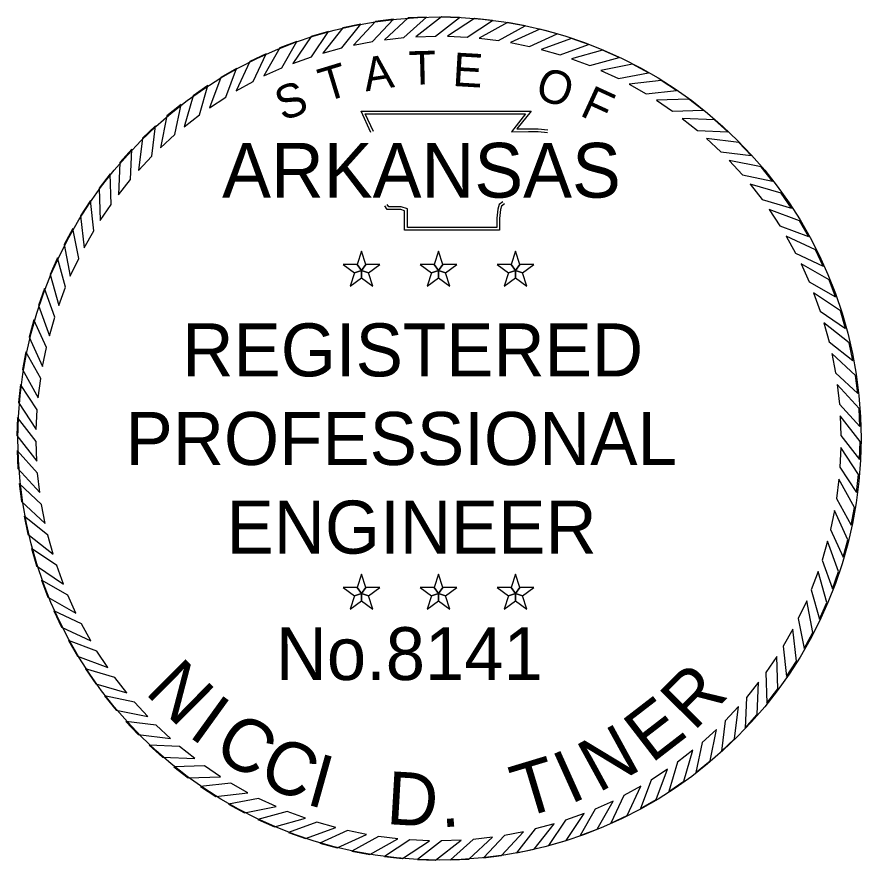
# Model space of a CAD drawing. Extents: x 0 to 19, y -0.6 to 11.2.
# Drawn here: x 17.822 to 19.023, y 9.084 to 10.284 of the extents above; entities that cross this region are included whole.
import ezdxf

# ---------------------------------------------------------------- set-up
doc = ezdxf.new("R2010")
doc.units = 0
doc.layers.add('G-ANNO-STMP', color=7, linetype='Continuous')
doc.layers.add('G-No Plot-Stamp-1', color=7, linetype='Continuous')

msp = doc.modelspace()

# ---------------------------------------------------------------- linework, layer by layer
at = {"layer": 'G-ANNO-STMP'}
for points in [[(18.3112, 10.2732), (18.2859, 10.2679), (18.2573, 10.2319), (18.2842, 10.2393)], [(18.3578, 10.2801), (18.3322, 10.2768), (18.3008, 10.2431), (18.3282, 10.2484)], [(18.4048, 10.2833), (18.379, 10.282), (18.3451, 10.2509), (18.3728, 10.254)], [(18.4519, 10.2828), (18.4261, 10.2835), (18.3899, 10.2552), (18.4177, 10.2561)], [(18.4988, 10.2786), (18.4732, 10.2813), (18.4348, 10.256), (18.4627, 10.2546)], [(18.5453, 10.2707), (18.5199, 10.2755), (18.4797, 10.2532), (18.5073, 10.2497)], [(18.2652, 10.2627), (18.2405, 10.2554), (18.2148, 10.2173), (18.241, 10.2268)], [(18.591, 10.2592), (18.5661, 10.266), (18.5242, 10.2469), (18.5515, 10.2412)], [(18.2203, 10.2486), (18.1962, 10.2394), (18.1735, 10.1994), (18.1989, 10.2109)], [(18.6356, 10.2442), (18.6113, 10.2529), (18.5681, 10.2371), (18.5949, 10.2294)], [(18.6789, 10.2257), (18.6554, 10.2362), (18.6111, 10.224), (18.6372, 10.2141)], [(18.1766, 10.2311), (18.1533, 10.22), (18.1338, 10.1783), (18.1582, 10.1918)], [(18.7207, 10.2039), (18.698, 10.2162), (18.6529, 10.2074), (18.6781, 10.1956)], [(18.1344, 10.2101), (18.112, 10.1973), (18.0959, 10.1542), (18.1192, 10.1695)], [(18.7606, 10.1788), (18.739, 10.1929), (18.6933, 10.1877), (18.7175, 10.1739)], [(18.0939, 10.1859), (18.0726, 10.1714), (18.06, 10.1272), (18.082, 10.1443)], [(18.7984, 10.1507), (18.778, 10.1665), (18.732, 10.1649), (18.7551, 10.1492)], [(18.0555, 10.1587), (18.0354, 10.1425), (18.0263, 10.0974), (18.0469, 10.1162)], [(18.0194, 10.1284), (18.0006, 10.1107), (17.995, 10.0651), (18.0141, 10.0854)], [(18.8339, 10.1197), (18.8148, 10.137), (18.7688, 10.1391), (18.7906, 10.1216)], [(18.8669, 10.0861), (18.8491, 10.1048), (18.8035, 10.1104), (18.8238, 10.0914)], [(17.9857, 10.0955), (17.9684, 10.0764), (17.9664, 10.0304), (17.9838, 10.0522)], [(18.8971, 10.0499), (18.8809, 10.07), (18.8358, 10.0792), (18.8546, 10.0586)], [(17.9547, 10.06), (17.939, 10.0396), (17.9406, 9.9936), (17.9562, 10.0167)], [(18.9244, 10.0115), (18.9098, 10.0328), (18.8656, 10.0455), (18.8827, 10.0235)], [(17.9266, 10.0222), (17.9125, 10.0006), (17.9177, 9.9549), (17.9315, 9.9791)], [(18.9485, 9.9711), (18.9357, 9.9935), (18.8926, 10.0096), (18.9079, 9.9863)], [(17.9016, 9.9823), (17.8892, 9.9596), (17.898, 9.9145), (17.9099, 9.9397)], [(18.9695, 9.9289), (18.9584, 9.9522), (18.9167, 9.9716), (18.9302, 9.9472)], [(18.3122, 9.9224), (18.3184, 9.9309), (18.3122, 9.9499), (18.3061, 9.9309)], [(18.4219, 9.9224), (18.4281, 9.9309), (18.4219, 9.9499), (18.4158, 9.9309)], [(18.5317, 9.9224), (18.5378, 9.9309), (18.5317, 9.9499), (18.5255, 9.9309)], [(17.8798, 9.9405), (17.8692, 9.917), (17.8815, 9.8727), (17.8913, 9.8987)], [(18.3122, 9.9224), (18.3061, 9.9309), (18.2861, 9.9309), (18.3023, 9.9192)], [(18.3122, 9.9224), (18.3222, 9.9192), (18.3383, 9.9309), (18.3184, 9.9309)], [(18.4219, 9.9224), (18.4158, 9.9309), (18.3958, 9.9309), (18.412, 9.9192)], [(18.4219, 9.9224), (18.4319, 9.9192), (18.448, 9.9309), (18.4281, 9.9309)], [(18.5317, 9.9224), (18.5255, 9.9309), (18.5056, 9.9309), (18.5217, 9.9192)], [(18.5317, 9.9224), (18.5416, 9.9192), (18.5577, 9.9309), (18.5378, 9.9309)], [(18.987, 9.8852), (18.9779, 9.9093), (18.9378, 9.9319), (18.9493, 9.9065)], [(18.3122, 9.9224), (18.3023, 9.9192), (18.2961, 9.9003), (18.3122, 9.912)], [(18.3122, 9.9224), (18.3122, 9.912), (18.3283, 9.9003), (18.3222, 9.9192)], [(18.4219, 9.9224), (18.412, 9.9192), (18.4058, 9.9003), (18.4219, 9.912)], [(18.4219, 9.9224), (18.4219, 9.912), (18.4381, 9.9003), (18.4319, 9.9192)], [(18.5317, 9.9224), (18.5217, 9.9192), (18.5155, 9.9003), (18.5317, 9.912)], [(18.5317, 9.9224), (18.5317, 9.912), (18.5478, 9.9003), (18.5416, 9.9192)], [(17.8613, 9.8972), (17.8526, 9.8729), (17.8683, 9.8297), (17.8761, 9.8564)], [(19.0011, 9.8402), (18.9939, 9.865), (18.9557, 9.8907), (18.9652, 9.8645)], [(17.8462, 9.8525), (17.8395, 9.8276), (17.8586, 9.7858), (17.8642, 9.8131)], [(19.0116, 9.7943), (19.0063, 9.8195), (18.9703, 9.8482), (18.9777, 9.8213)], [(17.8347, 9.8069), (17.83, 9.7815), (17.8523, 9.7413), (17.8558, 9.7689)], [(19.0185, 9.7477), (19.0152, 9.7733), (18.9816, 9.8046), (18.9868, 9.7772)], [(17.8269, 9.7604), (17.8241, 9.7347), (17.8495, 9.6964), (17.8508, 9.7242)], [(19.0217, 9.7007), (19.0204, 9.7264), (18.9893, 9.7603), (18.9924, 9.7326)], [(17.8227, 9.7135), (17.8219, 9.6877), (17.8503, 9.6514), (17.8494, 9.6793)], [(19.0212, 9.6536), (19.0219, 9.6793), (18.9936, 9.7156), (18.9945, 9.6877)], [(17.8222, 9.6664), (17.8235, 9.6406), (17.8545, 9.6067), (17.8515, 9.6344)], [(19.017, 9.6066), (19.0198, 9.6323), (18.9944, 9.6706), (18.9931, 9.6428)], [(19.0091, 9.5602), (19.0139, 9.5855), (18.9916, 9.6258), (18.9881, 9.5981)], [(17.8254, 9.6194), (17.8287, 9.5938), (17.8623, 9.5624), (17.8571, 9.5898)], [(18.9976, 9.5145), (19.0044, 9.5394), (18.9853, 9.5812), (18.9797, 9.5539)], [(17.8322, 9.5728), (17.8375, 9.5475), (17.8735, 9.5189), (17.8662, 9.5458)], [(18.9826, 9.4698), (18.9913, 9.4941), (18.9755, 9.5374), (18.9678, 9.5106)], [(17.8427, 9.5268), (17.85, 9.5021), (17.8881, 9.4764), (17.8787, 9.5026)], [(18.9641, 9.4265), (18.9747, 9.4501), (18.9624, 9.4944), (18.9525, 9.4683)], [(17.8568, 9.4819), (17.866, 9.4578), (17.906, 9.4351), (17.8946, 9.4605)], [(18.3122, 9.463), (18.3184, 9.4715), (18.3122, 9.4904), (18.3061, 9.4715)], [(18.4219, 9.463), (18.4281, 9.4715), (18.4219, 9.4904), (18.4158, 9.4715)], [(18.5317, 9.463), (18.5378, 9.4715), (18.5317, 9.4904), (18.5255, 9.4715)], [(18.3122, 9.463), (18.3061, 9.4715), (18.2861, 9.4715), (18.3023, 9.4598)], [(18.3122, 9.463), (18.3222, 9.4598), (18.3383, 9.4715), (18.3184, 9.4715)], [(18.4219, 9.463), (18.4158, 9.4715), (18.3958, 9.4715), (18.412, 9.4598)], [(18.4219, 9.463), (18.4319, 9.4598), (18.448, 9.4715), (18.4281, 9.4715)], [(18.5317, 9.463), (18.5255, 9.4715), (18.5056, 9.4715), (18.5217, 9.4598)], [(18.5317, 9.463), (18.5416, 9.4598), (18.5577, 9.4715), (18.5378, 9.4715)], [(18.3122, 9.463), (18.3023, 9.4598), (18.2961, 9.4408), (18.3122, 9.4525)], [(18.3122, 9.463), (18.3122, 9.4525), (18.3283, 9.4408), (18.3222, 9.4598)], [(18.4219, 9.463), (18.412, 9.4598), (18.4058, 9.4408), (18.4219, 9.4525)], [(18.4219, 9.463), (18.4219, 9.4525), (18.4381, 9.4408), (18.4319, 9.4598)], [(18.5317, 9.463), (18.5217, 9.4598), (18.5155, 9.4408), (18.5317, 9.4525)], [(18.5317, 9.463), (18.5317, 9.4525), (18.5478, 9.4408), (18.5416, 9.4598)], [(18.9423, 9.3848), (18.9546, 9.4074), (18.9459, 9.4526), (18.934, 9.4273)], [(17.8744, 9.4382), (17.8854, 9.4148), (17.9271, 9.3954), (17.9137, 9.4198)], [(18.9172, 9.3449), (18.9313, 9.3665), (18.9261, 9.4122), (18.9123, 9.3879)], [(17.8953, 9.3959), (17.9082, 9.3736), (17.9513, 9.3575), (17.9359, 9.3808)], [(18.8891, 9.307), (18.9049, 9.3275), (18.9033, 9.3734), (18.8876, 9.3504)], [(17.9195, 9.3555), (17.9341, 9.3342), (17.9783, 9.3215), (17.9612, 9.3436)], [(18.8582, 9.2715), (18.8755, 9.2907), (18.8775, 9.3366), (18.8601, 9.3149)], [(17.9468, 9.3171), (17.963, 9.297), (18.0081, 9.2879), (17.9893, 9.3085)], [(18.8245, 9.2386), (18.8432, 9.2563), (18.8489, 9.302), (18.8298, 9.2816)], [(17.977, 9.281), (17.9947, 9.2622), (18.0404, 9.2566), (18.02, 9.2757)], [(18.7883, 9.2084), (18.8084, 9.2246), (18.8176, 9.2696), (18.797, 9.2509)], [(18.01, 9.2473), (18.0291, 9.23), (18.075, 9.228), (18.0533, 9.2454)], [(18.7499, 9.1811), (18.7712, 9.1957), (18.7839, 9.2399), (18.7619, 9.2228)], [(18.0455, 9.2163), (18.0659, 9.2006), (18.1119, 9.2022), (18.0888, 9.2178)], [(18.7095, 9.1569), (18.7319, 9.1698), (18.748, 9.2128), (18.7247, 9.1975)], [(18.0833, 9.1882), (18.1049, 9.1741), (18.1506, 9.1793), (18.1264, 9.1931)], [(18.6673, 9.136), (18.6906, 9.147), (18.71, 9.1887), (18.6856, 9.1753)], [(18.1232, 9.1632), (18.1458, 9.1508), (18.191, 9.1596), (18.1657, 9.1714)], [(18.6236, 9.1184), (18.6477, 9.1276), (18.6703, 9.1676), (18.6449, 9.1561)], [(18.1649, 9.1413), (18.1885, 9.1308), (18.2328, 9.1431), (18.2067, 9.1529)], [(18.5786, 9.1043), (18.6034, 9.1116), (18.6291, 9.1497), (18.6029, 9.1403)], [(18.2083, 9.1228), (18.2326, 9.1142), (18.2758, 9.1299), (18.249, 9.1377)], [(18.5327, 9.0938), (18.5579, 9.0991), (18.5866, 9.1351), (18.5597, 9.1278)], [(18.2529, 9.1078), (18.2778, 9.1011), (18.3197, 9.1201), (18.2924, 9.1258)], [(18.4861, 9.0869), (18.5117, 9.0903), (18.543, 9.1239), (18.5157, 9.1187)], [(18.2986, 9.0963), (18.324, 9.0916), (18.3642, 9.1139), (18.3365, 9.1173)], [(18.345, 9.0885), (18.3707, 9.0857), (18.4091, 9.1111), (18.3812, 9.1124)], [(18.392, 9.0843), (18.4178, 9.0835), (18.454, 9.1118), (18.4261, 9.1109)], [(18.4391, 9.0837), (18.4649, 9.085), (18.4988, 9.1161), (18.4711, 9.113)]]:
    msp.add_lwpolyline(points, close=True, dxfattribs=at)
for points in [[(18.3258, 10.119), (18.3118, 10.1493), (18.5538, 10.1494), (18.5336, 10.124), (18.5501, 10.1242), (18.5638, 10.1244), (18.5775, 10.1229)], [(18.3293, 10.1206), (18.3178, 10.1455), (18.5459, 10.1456), (18.5256, 10.1201), (18.5501, 10.1204), (18.5636, 10.1206), (18.5771, 10.1191)], [(18.5133, 10.0205), (18.5082, 10.0164), (18.5064, 10.0099), (18.505, 9.9969), (18.505, 9.9838), (18.3776, 9.9838), (18.3776, 10.0025), (18.3776, 10.0104), (18.3688, 10.013), (18.3511, 10.013), (18.3488, 10.0165)], [(18.5157, 10.0176), (18.5116, 10.0142), (18.5102, 10.0092), (18.5088, 9.9966), (18.5088, 9.9799), (18.3737, 9.9799), (18.3737, 10.0025), (18.3737, 10.0075), (18.3683, 10.0092), (18.349, 10.0092), (18.3456, 10.0144)]]:
    msp.add_lwpolyline(points, dxfattribs=at)
at = {"layer": 'G-No Plot-Stamp-1'}
msp.add_circle((18.4233, 9.6835), 0.6, dxfattribs=at)

# ---------------------------------------------------------------- texts
at = {"layer": 'G-ANNO-STMP'}
for s, height, rotation, p in [('A', 0.0477, 8.6788, (18.3184, 10.1773)), ('T', 0.0477, 1.4789, (18.3801, 10.1868)), ('E', 0.0477, 356.672, (18.4412, 10.1853)), ('T', 0.0477, 16.9015, (18.2605, 10.1621)), ('O', 0.0477, 341.2218, (18.5571, 10.1689)), ('S', 0.0477, 19.7726, (18.1998, 10.1349)), ('F', 0.0477, 335.3628, (18.6214, 10.1438)), ('N', 0.0754, 315.2676, (18.0028, 9.3216)), ('R', 0.0754, 45.478, (18.7853, 9.2657)), ('I', 0.0754, 324.2141, (18.0641, 9.2609)), ('E', 0.0754, 37.6498, (18.725, 9.2201)), ('C', 0.0754, 328.6873, (18.0982, 9.2342)), ('N', 0.0754, 28.7033, (18.6493, 9.1786)), ('C', 0.0754, 336.5155, (18.1624, 9.1943)), ('I', 0.0754, 24.2301, (18.6092, 9.1624)), ('I', 0.0754, 344.3437, (18.2314, 9.1635)), ('T', 0.0754, 16.7747, (18.54, 9.1425)), ('D', 0.0754, 356.6451, (18.3466, 9.1349)), ('.', 0.0754, 4.846, (18.4256, 9.1298))]:
    msp.add_text(s, height=height, rotation=rotation, dxfattribs=at).set_placement(p)
for s, height, p in [('ARKANSAS', 0.07791, (18.114, 10.0263)), ('REGISTERED', 0.07543, (18.0574, 9.7719)), ('PROFESSIONAL', 0.07543, (17.9765, 9.6458)), ('ENGINEER', 0.07543, (18.1202, 9.5197)), ('No.8141', 0.07513, (18.1905, 9.3398))]:
    msp.add_text(s, height=height, dxfattribs=at).set_placement(p)

doc.saveas('drawing.dxf')
